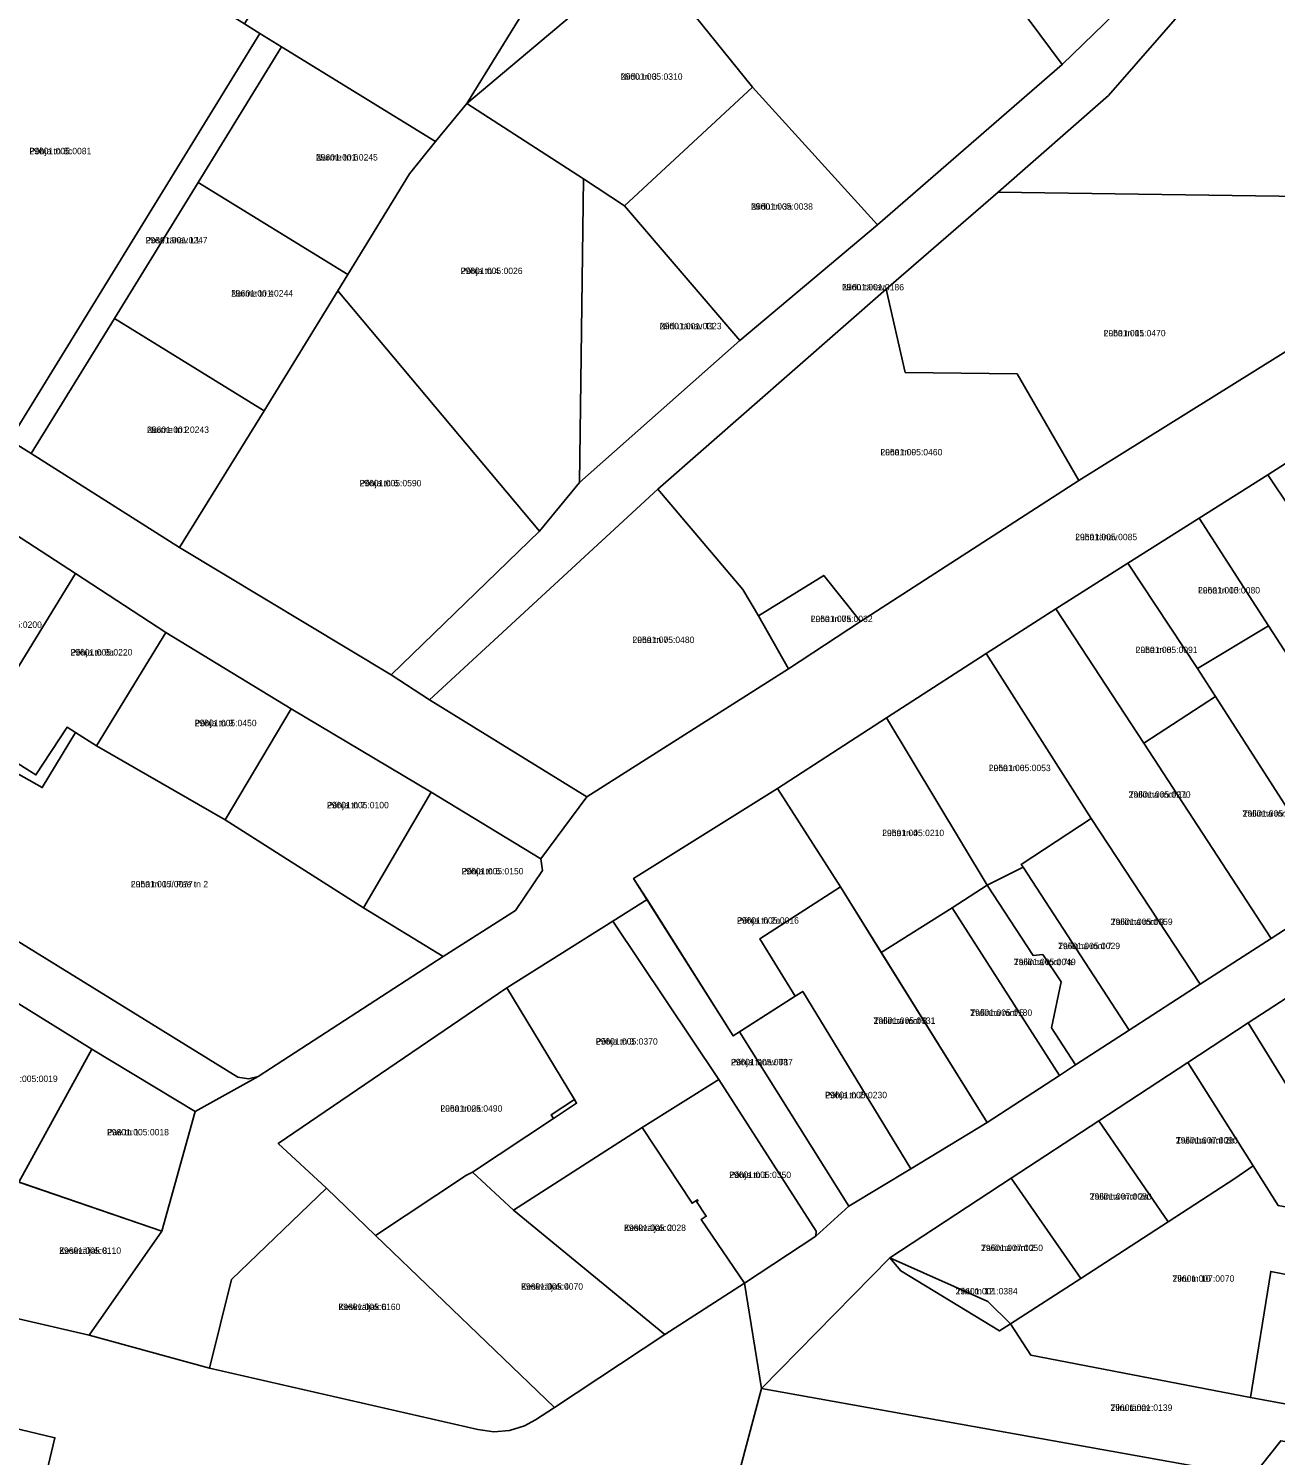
# Model space of a CAD drawing. Extents: x 518839 to 525192, y 6573164 to 6576561.
# Drawn here: x 524230.2 to 524522.2, y 6574516.4 to 6574850.6 of the extents above; entities that cross this region are included whole.
import ezdxf

# ---------------------------------------------------------------- set-up
doc = ezdxf.new("R2010")
doc.units = 0
for name, color, linetype in [('L_AADRESS', 7, 'Continuous'), ('PIIR', 7, 'Continuous'), ('TUNNUS', 7, 'Continuous')]:
    doc.layers.add(name, color=color, linetype=linetype)

msp = doc.modelspace()

# ---------------------------------------------------------------- linework, layer by layer
at = {"layer": 'PIIR'}
for points in [[(524395.95, 6574935.2), (524433.36, 6574918.41), (524467.08, 6574908.9), (524494.46, 6574895.61), (524516.52, 6574885.17), (524472.25, 6574842.16), (524422.43, 6574909.22), (524374.53, 6574868.17), (524332.8, 6574833.07), (524353.67, 6574866.88)], [(524374.53, 6574868.17), (524422.43, 6574909.22), (524472.25, 6574842.16), (524429.03, 6574804.68), (524399.71, 6574836.87)], [(524280.75, 6574851.75), (524307.24, 6574895.13), (524353.67, 6574866.88), (524332.8, 6574833.07), (524325.53, 6574824.16), (524289.45, 6574846.37), (524284.34, 6574849.49)], [(524349.87, 6574732.89), (524359.23, 6574744.29), (524396.75, 6574777.58), (524429.03, 6574804.68), (524472.25, 6574842.16), (524516.52, 6574885.17), (524538.41, 6574874.85), (524560.53, 6574864.54), (524577.14, 6574856.56), (524584.79, 6574857.73), (524596.22, 6574854.46), (524600.32, 6574852.95), (524596.49, 6574845.07), (524547.26, 6574863.55), (524507.92, 6574863.47), (524483.08, 6574834.9), (524457.28, 6574812.27), (524431.07, 6574789.59), (524377.56, 6574742.71), (524324.1, 6574693.4), (524315.12, 6574699.28)], [(524231.52, 6574882.44), (524280.75, 6574851.75), (524284.34, 6574849.49), (524225.78, 6574754.21), (524176.45, 6574785.3), (524219.36, 6574860.08), (524218.07, 6574860.82)], [(524332.8, 6574833.07), (524374.53, 6574868.17), (524399.71, 6574836.87), (524369.73, 6574809.06), (524360.17, 6574815.39)], [(524483.08, 6574834.9), (524507.92, 6574863.47), (524547.26, 6574863.55), (524596.49, 6574845.07), (524569.32, 6574805.16), (524558.58, 6574796.1), (524534, 6574811.24), (524457.28, 6574812.27)], [(524225.78, 6574754.21), (524284.34, 6574849.49), (524289.45, 6574846.37), (524269.9, 6574814.59), (524250.32, 6574782.71), (524230.79, 6574751.08)], [(524269.9, 6574814.59), (524289.45, 6574846.37), (524325.53, 6574824.16), (524319.43, 6574816.57), (524304.99, 6574793.05)], [(524429.03, 6574804.68), (524396.75, 6574777.58), (524369.73, 6574809.06), (524399.71, 6574836.87)], [(524319.43, 6574816.57), (524325.53, 6574824.16), (524332.8, 6574833.07), (524360.17, 6574815.39), (524359.23, 6574744.29), (524349.87, 6574732.89), (524302.6, 6574789.15), (524304.99, 6574793.05)], [(524250.32, 6574782.71), (524269.9, 6574814.59), (524304.99, 6574793.05), (524302.6, 6574789.15), (524285.34, 6574761.11)], [(524360.17, 6574815.39), (524369.73, 6574809.06), (524396.75, 6574777.58), (524359.23, 6574744.29)], [(524461.68, 6574769.71), (524435.5, 6574770.07), (524431.07, 6574789.59), (524457.28, 6574812.27), (524534, 6574811.24), (524558.58, 6574796.1), (524476.15, 6574744.79)], [(524265.55, 6574729.1), (524285.34, 6574761.11), (524302.6, 6574789.15), (524349.87, 6574732.89), (524315.12, 6574699.28)], [(524435.5, 6574770.07), (524461.68, 6574769.71), (524476.15, 6574744.79), (524424.99, 6574711.72), (524416.42, 6574722.53), (524401.13, 6574713.03), (524397.49, 6574719.22), (524377.56, 6574742.71), (524431.07, 6574789.59)], [(524230.79, 6574751.08), (524250.32, 6574782.71), (524285.34, 6574761.11), (524265.55, 6574729.1)], [(524537.6, 6574757.06), (524549.35, 6574738.65), (524552.94, 6574732.54), (524536.72, 6574721.74), (524520.43, 6574746.1)], [(524504.36, 6574735.95), (524520.43, 6574746.1), (524536.72, 6574721.74), (524570.42, 6574668.67), (524554.52, 6574658.36), (524520.57, 6574710.7)], [(524324.1, 6574693.4), (524377.56, 6574742.71), (524397.49, 6574719.22), (524401.13, 6574713.03), (524408.16, 6574700.66), (524360.94, 6574670.71)], [(524241.17, 6574722.95), (524217.72, 6574684.73), (524196.48, 6574698.11), (524220.39, 6574736.48)], [(524487.59, 6574725.41), (524504.36, 6574735.95), (524520.57, 6574710.7), (524503.93, 6574700.73)], [(524470.79, 6574714.71), (524487.59, 6574725.41), (524503.93, 6574700.73), (524508.14, 6574694.17), (524491.36, 6574683.23)], [(524262.33, 6574709.16), (524246.08, 6574682.62), (524241.16, 6574685.74), (524239.21, 6574686.98), (524231.92, 6574675.79), (524217.72, 6574684.73), (524241.17, 6574722.95)], [(524424.99, 6574711.72), (524408.16, 6574700.66), (524401.13, 6574713.03), (524416.42, 6574722.53)], [(524470.79, 6574714.71), (524491.36, 6574683.23), (524521.22, 6574637.52), (524504.58, 6574626.79), (524479.04, 6574665.61), (524454.42, 6574704.23)], [(524291.73, 6574691.3), (524276.28, 6574665.26), (524246.08, 6574682.62), (524262.33, 6574709.16)], [(524554.52, 6574658.36), (524537.64, 6574648.16), (524508.14, 6574694.17), (524503.93, 6574700.73), (524520.57, 6574710.7)], [(524431.09, 6574689.17), (524454.42, 6574704.23), (524479.04, 6574665.61), (524462.66, 6574654.85), (524463.1, 6574654.18), (524454.66, 6574649.96)], [(524217.72, 6574684.73), (524231.92, 6574675.79), (524239.21, 6574686.98), (524241.16, 6574685.74), (524233.39, 6574672.85), (524217.96, 6574681.51), (524196.21, 6574694.32), (524196.48, 6574698.11)], [(524196.21, 6574694.32), (524217.96, 6574681.51), (524233.39, 6574672.85), (524241.16, 6574685.74), (524246.08, 6574682.62), (524276.28, 6574665.26), (524308.67, 6574644.68), (524327.26, 6574633.24), (524283.95, 6574605.15), (524281.69, 6574604.63), (524279.22, 6574605.04), (524182.69, 6574664.61), (524181.94, 6574669.54)], [(524491.36, 6574683.23), (524508.14, 6574694.17), (524537.64, 6574648.16), (524521.22, 6574637.52)], [(524291.73, 6574691.3), (524324.45, 6574671.77), (524308.67, 6574644.68), (524276.28, 6574665.26)], [(524431.09, 6574689.17), (524454.66, 6574649.96), (524446.47, 6574644.67), (524429.87, 6574634.25), (524420.31, 6574649.6), (524405.57, 6574672.64)], [(524308.67, 6574644.68), (524324.45, 6574671.77), (524350.19, 6574656.17), (524350.59, 6574653.42), (524344.27, 6574644.07), (524327.26, 6574633.24)], [(524420.31, 6574649.6), (524401.45, 6574637.44), (524409.69, 6574623.98), (524395.21, 6574614.67), (524371.89, 6574651.58), (524405.57, 6574672.64)], [(524462.66, 6574654.85), (524479.04, 6574665.61), (524504.58, 6574626.79), (524487.94, 6574616.05), (524463.1, 6574654.18)], [(524487.94, 6574616.05), (524475.37, 6574607.92), (524469.76, 6574616.56), (524472.02, 6574627.34), (524467.7, 6574633.76), (524465.44, 6574633.51), (524454.66, 6574649.96), (524463.1, 6574654.18)], [(524436.8, 6574583.54), (524411.5, 6574625.08), (524409.69, 6574623.98), (524401.45, 6574637.44), (524420.31, 6574649.6), (524454.69, 6574594.37)], [(524446.47, 6574644.67), (524454.66, 6574649.96), (524465.44, 6574633.51), (524467.7, 6574633.76), (524472.02, 6574627.34), (524469.76, 6574616.56), (524475.37, 6574607.92), (524471.59, 6574605.43)], [(524367.02, 6574641.52), (524375.04, 6574646.59), (524395.21, 6574614.67), (524396.66, 6574615.6), (524422.33, 6574574.76), (524414.54, 6574567.79), (524414.61, 6574568.91), (524391.87, 6574604.46)], [(524454.69, 6574594.37), (524429.87, 6574634.25), (524446.47, 6574644.67), (524471.59, 6574605.43)], [(524342.2, 6574625.97), (524367.02, 6574641.52), (524391.87, 6574604.46), (524373.92, 6574593.25), (524343.76, 6574573.9), (524334.19, 6574582.78), (524353.16, 6574595.35), (524358.54, 6574598.92), (524358.04, 6574599.75)], [(524204.8, 6574590.02), (524206.59, 6574609.4), (524200.01, 6574612.98), (524209.08, 6574633.84), (524245.02, 6574611.56), (524227.93, 6574580.41), (524221.35, 6574582.67)], [(524515.81, 6574617.7), (524540.05, 6574633.54), (524559.31, 6574602.05), (524535.06, 6574586.49)], [(524288.67, 6574589.51), (524342.2, 6574625.97), (524358.04, 6574599.75), (524352.58, 6574596.19), (524353.16, 6574595.35), (524334.19, 6574582.78), (524332.72, 6574582.09), (524311.46, 6574567.9), (524299.94, 6574579.02)], [(524422.33, 6574574.76), (524396.66, 6574615.6), (524409.69, 6574623.98), (524411.5, 6574625.08), (524436.8, 6574583.54)], [(524501.66, 6574608.47), (524515.81, 6574617.7), (524535.06, 6574586.49), (524544.6, 6574570.79), (524535.57, 6574572.56), (524522.8, 6574574.95), (524516.96, 6574584.21)], [(524227.93, 6574580.41), (524245.02, 6574611.56), (524269.21, 6574596.94), (524261.43, 6574568.93)], [(524480.8, 6574594.78), (524501.66, 6574608.47), (524516.96, 6574584.21), (524512.72, 6574581.27), (524497.1, 6574571.15)], [(524391.87, 6574604.46), (524414.61, 6574568.91), (524414.54, 6574567.79), (524397.88, 6574556.77), (524387.75, 6574571.68), (524388.91, 6574572.44), (524386.62, 6574575.89), (524386.97, 6574576.12), (524386.84, 6574576.32), (524385.57, 6574575.49), (524373.92, 6574593.25)], [(524460.32, 6574581.35), (524480.8, 6574594.78), (524497.1, 6574571.15), (524476.63, 6574557.88)], [(524385.57, 6574575.49), (524386.84, 6574576.32), (524386.97, 6574576.12), (524386.62, 6574575.89), (524388.91, 6574572.44), (524387.75, 6574571.68), (524397.88, 6574556.77), (524379.18, 6574544.74), (524343.76, 6574573.9), (524373.92, 6574593.25)], [(524460.17, 6574547.21), (524476.63, 6574557.88), (524497.1, 6574571.15), (524512.72, 6574581.27), (524516.96, 6574584.21), (524522.8, 6574574.95), (524535.57, 6574572.56), (524533.12, 6574557.13), (524521.11, 6574559.5), (524516.34, 6574529.97), (524464.93, 6574539.89)], [(524261.43, 6574568.93), (524244.4, 6574544.59), (524214.28, 6574551.57), (524221.35, 6574582.67)], [(524332.72, 6574582.09), (524334.19, 6574582.78), (524343.76, 6574573.9), (524379.18, 6574544.74), (524353.34, 6574527.67), (524311.46, 6574567.9)], [(524431.89, 6574562.69), (524460.32, 6574581.35), (524476.63, 6574557.88), (524460.17, 6574547.21), (524454.82, 6574552.5)], [(524277.69, 6574557.6), (524299.94, 6574579.02), (524311.46, 6574567.9), (524353.34, 6574527.67), (524348.95, 6574524.74), (524346.35, 6574523.31), (524342.85, 6574522.23), (524339.19, 6574521.92), (524335.38, 6574522.49), (524272.61, 6574536.87)], [(524521.11, 6574559.5), (524533.12, 6574557.13), (524535.57, 6574572.56), (524544.6, 6574570.79), (524551.37, 6574560.62), (524561.57, 6574544.39), (524568.74, 6574533.17), (524555.31, 6574522.82), (524516.34, 6574529.97)], [(524401.81, 6574532.13), (524431.89, 6574562.69), (524434.43, 6574559.64), (524457.58, 6574545.58), (524460.17, 6574547.21), (524464.93, 6574539.89), (524516.34, 6574529.97), (524555.31, 6574522.82), (524565.29, 6574520.99), (524564.47, 6574513.44), (524561.67, 6574485.75), (524560.44, 6574467.33), (524557.14, 6574442.73), (524546.99, 6574446.75), (524554.43, 6574509.27), (524547.65, 6574515.75), (524523.42, 6574519.87), (524516.79, 6574511.45)], [(524460.17, 6574547.21), (524457.58, 6574545.58), (524434.43, 6574559.64), (524431.89, 6574562.69), (524454.82, 6574552.5)], [(524165.75, 6574537.51), (524236.37, 6574520.54), (524231.72, 6574501.21), (524205.78, 6574488.03), (524201.49, 6574497.08), (524191.56, 6574499.32), (524167.64, 6574487.97), (524165.87, 6574493.59), (524157.06, 6574490.89), (524159.65, 6574484.94), (524164.05, 6574486.32), (524171.13, 6574471.57), (524163.19, 6574467.21), (524149.18, 6574496.1), (524149.94, 6574510.31), (524161.44, 6574518.56)], [(524401.81, 6574532.13), (524516.79, 6574511.45), (524523.42, 6574519.87), (524547.65, 6574515.75), (524554.43, 6574509.27), (524546.99, 6574446.75), (524456.99, 6574455.07), (524385.14, 6574469.23)]]:
    msp.add_lwpolyline(points, close=True, dxfattribs=at)
for points in [[(524537.6, 6574757.06), (524520.43, 6574746.1), (524504.36, 6574735.95), (524487.59, 6574725.41), (524470.79, 6574714.71), (524454.42, 6574704.23), (524431.09, 6574689.17), (524405.57, 6574672.64), (524371.89, 6574651.58), (524375.04, 6574646.59), (524367.02, 6574641.52), (524342.2, 6574625.97), (524288.67, 6574589.51), (524299.94, 6574579.02), (524277.69, 6574557.6), (524272.61, 6574536.87), (524244.4, 6574544.59), (524261.43, 6574568.93), (524269.21, 6574596.94), (524283.95, 6574605.15), (524327.26, 6574633.24), (524344.27, 6574644.07), (524350.59, 6574653.42), (524350.19, 6574656.17), (524360.94, 6574670.71), (524408.16, 6574700.66), (524424.99, 6574711.72), (524476.15, 6574744.79), (524558.58, 6574796.1)], [(524225.78, 6574754.21), (524230.79, 6574751.08), (524265.55, 6574729.1), (524315.12, 6574699.28), (524324.1, 6574693.4), (524360.94, 6574670.71), (524350.19, 6574656.17), (524324.45, 6574671.77), (524291.73, 6574691.3), (524262.33, 6574709.16), (524241.17, 6574722.95), (524220.39, 6574736.48)], [(524182.69, 6574664.61), (524279.22, 6574605.04), (524281.69, 6574604.63), (524283.95, 6574605.15), (524269.21, 6574596.94), (524245.02, 6574611.56), (524209.08, 6574633.84)], [(524540.05, 6574633.54), (524515.81, 6574617.7), (524501.66, 6574608.47), (524480.8, 6574594.78), (524460.32, 6574581.35), (524431.89, 6574562.69), (524401.81, 6574532.13), (524397.88, 6574556.77), (524414.54, 6574567.79), (524422.33, 6574574.76), (524436.8, 6574583.54), (524454.69, 6574594.37), (524471.59, 6574605.43), (524475.37, 6574607.92), (524487.94, 6574616.05), (524504.58, 6574626.79), (524521.22, 6574637.52), (524537.64, 6574648.16)], [(524214.28, 6574551.57), (524244.4, 6574544.59), (524272.61, 6574536.87), (524335.38, 6574522.49), (524339.19, 6574521.92), (524342.85, 6574522.23), (524346.35, 6574523.31), (524348.95, 6574524.74), (524353.34, 6574527.67), (524379.18, 6574544.74), (524397.88, 6574556.77), (524401.81, 6574532.13), (524385.14, 6574469.23)], [(524228.42, 6574481.2), (524231.72, 6574501.21), (524236.37, 6574520.54), (524165.75, 6574537.51)]]:
    msp.add_lwpolyline(points, dxfattribs=at)

# ---------------------------------------------------------------- texts
at = {"layer": 'L_AADRESS'}
for s, p in [('Niidu tn 3', (524368.85, 6574838.62)), ('Põhja tn 8c', (524230.4, 6574821.18)), ('Nurme tn 6', (524297.5, 6574819.71)), ('Niidu tn 3a', (524399.38, 6574808.18)), ('Posti tänav L1', (524257.62, 6574800.3)), ('Põhja tn 4', (524331.39, 6574793.11)), ('Nurme tn 4', (524277.64, 6574787.85)), ('Niidu tänav', (524420.71, 6574789.29)), ('Niidu tänav T1', (524377.99, 6574780.19)), ('Luha tn 11', (524481.97, 6574778.53)), ('Nurme tn 2', (524257.95, 6574755.91)), ('Luha tn 9', (524429.69, 6574750.65)), ('Põhja tn 6', (524307.71, 6574743.4)), ('Luha tänav', (524475.31, 6574730.78)), ('Luha tn 10', (524504.08, 6574718.3)), ('Luha tn 7a', (524413.37, 6574711.6)), ('Luha tn 7', (524371.63, 6574706.71)), ('Põhja tn 9a', (524240.02, 6574703.77)), ('Luha tn 8', (524489.46, 6574704.35)), ('Põhja tn 9', (524269.1, 6574687.21)), ('Luha tn 6', (524455.07, 6574676.69)), ('Tallinna mnt 11', (524487.82, 6574670.46)), ('Põhja tn 7', (524300.07, 6574667.99)), ('Tallinna mnt 13', (524514.5, 6574666.03)), ('Luha tn 4', (524430.11, 6574661.47)), ('Põhja tn 5', (524331.6, 6574652.5)), ('Luha tn 1 // Pae tn 2', (524254.17, 6574649.48)), ('Põhja tn 2a', (524396.1, 6574640.98)), ('Tallinna mnt 9', (524483.62, 6574640.66)), ('Tallinna mnt 7', (524471.3, 6574635)), ('Tallinna mnt 7a', (524460.92, 6574631.25)), ('Tallinna mnt 5', (524450.73, 6574619.37)), ('Tallinna mnt 3', (524428.07, 6574617.5)), ('Põhja tn 3', (524363.03, 6574612.64)), ('Põhja tänav T1', (524394.68, 6574607.8)), ('Põhja tn 2', (524416.73, 6574600.08)), ('Luha tn 2a', (524326.65, 6574596.93)), ('Pae tn 1', (524248.57, 6574591.38)), ('Tallinna mnt 2b', (524498.88, 6574589.47)), ('Põhja tn 1', (524394.27, 6574581.4)), ('Tallinna mnt 2a', (524478.71, 6574576.32)), ('Keskväljak 2', (524369.65, 6574568.99)), ('Keskväljak 8', (524237.37, 6574563.63)), ('Tallinna mnt 2', (524453.25, 6574564.28)), ('Tiiru tn 10', (524498.07, 6574557.09)), ('Keskväljak 4', (524345.55, 6574555.23)), ('Tiiru tn 12', (524447.32, 6574554.13)), ('Keskväljak 6', (524302.77, 6574550.47)), ('Tiiru tänav', (524483.55, 6574526.86))]:
    msp.add_text(s, height=1.5, dxfattribs=at).set_placement(p)
at = {"layer": 'TUNNUS'}
for s, p in [('29601:005:0310', (524368.85, 6574838.62)), ('29601:005:0081', (524230.4, 6574821.18)), ('29601:001:0245', (524297.5, 6574819.71)), ('29601:005:0038', (524399.38, 6574808.18)), ('29601:001:0247', (524257.62, 6574800.3)), ('29601:005:0026', (524331.39, 6574793.11)), ('29601:001:0244', (524277.64, 6574787.85)), ('29601:001:0186', (524420.71, 6574789.29)), ('29601:001:0323', (524377.99, 6574780.19)), ('29601:005:0470', (524481.97, 6574778.53)), ('29601:001:0243', (524257.95, 6574755.91)), ('29601:005:0460', (524429.69, 6574750.65)), ('29601:005:0590', (524307.71, 6574743.4)), ('29601:005:0085', (524475.31, 6574730.78)), ('29601:005:0080', (524504.08, 6574718.3)), ('29601:005:0200', (524218.82, 6574710.25)), ('29601:005:0032', (524413.37, 6574711.6)), ('29601:005:0480', (524371.63, 6574706.71)), ('29601:005:0220', (524240.02, 6574703.77)), ('29601:005:0091', (524489.46, 6574704.35)), ('29601:005:0450', (524269.1, 6574687.21)), ('29601:005:0053', (524455.07, 6574676.69)), ('29601:005:0270', (524487.82, 6574670.46)), ('29601:005:0100', (524300.07, 6574667.99)), ('29601:005:0089', (524514.5, 6574666.03)), ('29601:005:0210', (524430.11, 6574661.47)), ('29601:005:0077', (524254.17, 6574649.48)), ('29601:005:0150', (524331.6, 6574652.5)), ('29601:005:0016', (524396.1, 6574640.98)), ('29601:005:0059', (524483.62, 6574640.66)), ('29601:005:0029', (524471.3, 6574635)), ('29601:005:0049', (524460.92, 6574631.25)), ('29601:005:0180', (524450.73, 6574619.37)), ('29601:005:0031', (524428.07, 6574617.5)), ('29601:005:0370', (524363.03, 6574612.64)), ('29601:005:0087', (524394.68, 6574607.8)), ('29601:005:0019', (524222.52, 6574603.89)), ('29601:005:0230', (524416.73, 6574600.08)), ('29601:005:0490', (524326.65, 6574596.93)), ('29601:005:0018', (524248.57, 6574591.38)), ('29601:007:0090', (524498.88, 6574589.47)), ('29601:005:0350', (524394.27, 6574581.4)), ('29601:007:0080', (524478.71, 6574576.32)), ('29601:005:0028', (524369.65, 6574568.99)), ('29601:005:0110', (524237.37, 6574563.63)), ('29601:007:0050', (524453.25, 6574564.28)), ('29601:007:0070', (524498.07, 6574557.09)), ('29601:005:0070', (524345.55, 6574555.23)), ('29601:001:0384', (524447.32, 6574554.13)), ('29601:005:0160', (524302.77, 6574550.47)), ('29601:001:0139', (524483.55, 6574526.86))]:
    msp.add_text(s, height=1.5, dxfattribs=at).set_placement(p)

doc.saveas('drawing.dxf')
